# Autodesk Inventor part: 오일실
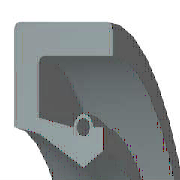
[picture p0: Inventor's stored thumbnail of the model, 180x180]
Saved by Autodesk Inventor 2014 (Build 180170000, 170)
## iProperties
IsCustomPart: 1
Created: 2015-10
Part Number: 오일실
Material: Rubber
Description: 오일-실
Document SubType Name: Modeling
Standard: KS B 2804
Designer: mdu
Standards Organization: KS
Language: ko-KR
Size Designation: S - 25 38 8
Categories: <MemberInstance><Categories><Category DisplayName="샤프트 부품" InternalName="7f7aeb1f-a693-4053-b835-cee3144e0d98" Mnemonic="SHFT"><Category DisplayName="실링" Intern
Density: 0.93 g/cm^3
Appearance: Rubber - Black - Version 1.1
Mass: 2.23721 g
Surface Area: 37.0166 cm^2
Volume: 2.4056 cm^3
Author: mdu
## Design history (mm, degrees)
revolve "본체" stored, may be unused: angle "d17" = 90 deg
revolve "스프링1" stored, may be unused: angle "d18" = 90 deg
body "Solid1"
sketch "스케치1"
  geometry: L1 (0, 19)-(8, 19); L2 (8, 19)-(8, 17.75); L3 (8, 17.75)-(1.75, 17.75); L4 (0, 19)-(0, 14.6); L5 (0, 14.6)-(1.75, 14.25); L6 (1.75, 14.25)-(4.9, 12.5); L7 (4.9, 12.5)-(0, 12.5); L8 (6.3, 13.375)-(6.3, 14.6); L9 (0, 0)-(9.586, 0) reference; L10 (4.9, 12.5)-(6.3, 13.375); L11 (0, 18)-(0, -3) reference; L12 (-1.917, 0)-(11.503, 0) reference; L13 (4.2, 14.6)-(1.75, 15.09); L14 (1.75, 15.09)-(1.75, 17.75); L15 (6.3, 14.6)-(5.6, 14.6); C1 r 0.455 at (4.9, 14.6); A1 r 0.7 centre (4.9, 14.6) between (5.6, 14.6) and (4.2, 14.6)
  constraints: 26 end point, 5 horizontal alignment, 4 perpendicular, 2 centre point, 2 collinear, 2 horizontal, 2 parallel, 2 point on circle, 2 point on line, 2 vertical alignment, 1 coincident
  dimensions: "d0" = 38 diameter of L1 L9 (= SD2); "d1" = 26.75 diameter of L8.start L9 (= ABDM); "d2" = 1.25 distance of L1.end L2.end (computed from SD); "d3" = 0.91 diameter of C1 (= SPDI); "d4" = 1.4 diameter of A1 (= SPDA); "d5" = 25 diameter of L6.end L9 (= NND); "d6" = 28.5 diameter of L5.end L9 (= TKDM); "d7" = 29.2 diameter of L4.end L9 (= HLDM); "d8" = 4.9 distance from line of C1.centre L4 (= SPDST); "d9" = 6.3 distance between parallel lines of L8 L4 (= SDI); "d10" = 8 distance between parallel lines of L2 L4 (= SWDT); "d12" = 1.75 distance between parallel lines of L14 L4 (= SD)
fillet "모깎기1" dims "d11" = 0.3 (= RR)
other parameters: "SD2" = 38 [user parameter; used in 1 equation term], "SWDT" = 8 [user parameter; used in 1 equation term], "RR" = 0.3 [user parameter; used in 1 equation term], "SD" = 1.75 [user parameter; used in 2 equation terms], "NND" = 25 [user parameter; used in 1 equation term], "SPDA" = 1.4 [user parameter; used in 1 equation term], "SPDI" = 0.91 [user parameter; used in 1 equation term], "TKDM" = 28.5 [user parameter; used in 1 equation term], "HLDM" = 29.2 [user parameter; used in 1 equation term], "ABDM" = 26.75 [user parameter; used in 1 equation term], "SDI" = 6.3 [user parameter; used in 1 equation term], "SPDST" = 4.9 [user parameter; used in 1 equation term], "d13" = 0, "d14" = 0, "d15" = 0, "LAB" = 0.35 [user parameter]
